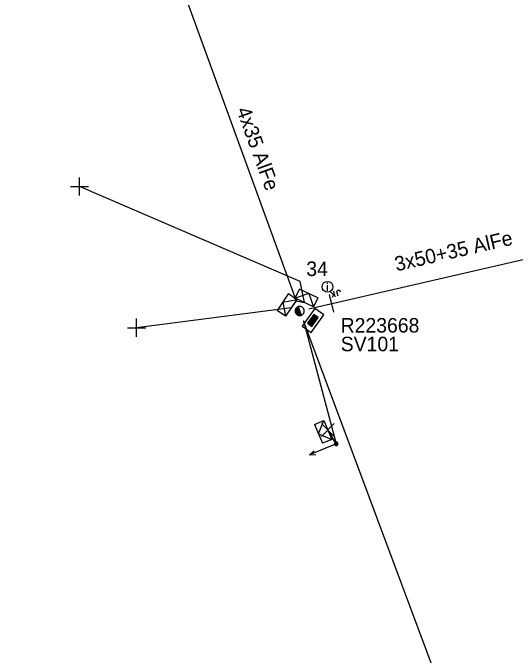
# Model space of a CAD drawing. Extents: x -536148 to -535465, y -1201639 to -1201298.
# Drawn here: x -535581.57 to -535546.95, y -1201567.67 to -1201523.39 of the extents above; entities that cross this region are included whole.
import ezdxf

# ---------------------------------------------------------------- set-up
doc = ezdxf.new("R2010")
doc.units = 0
for name, color, linetype in [('CHRAN_NN', 7, 'Continuous'), ('CIZÍ_NADZEM_POPIS', 7, 'Continuous'), ('CIZÍ_PODZEM', 7, 'Continuous'), ('CIZÍ_PODZEM_POPIS', 7, 'Continuous'), ('DOPLŇ_POPISY', 7, 'Continuous'), ('ELE_EON', 7, 'Continuous'), ('ELE_EON_POPIS', 7, 'Continuous'), ('KN_HRAN_POHYBLIVÁ', 7, 'Continuous'), ('KN_VKP_HRAN_', 7, 'Continuous'), ('KN_VKP_HRAN_NEZNATELNÁ', 7, 'Continuous'), ('KN_VKP_HRAN_PARCEL_NEVIDITELNÁ', 7, 'Continuous'), ('KN_VKP_HRAN_SPORNÁ', 7, 'Continuous'), ('OP KABELU NN', 7, 'Continuous'), ('PB_NN_POPIS', 7, 'Continuous'), ('PK_HRAN_POHYBLIVÁ', 7, 'Continuous'), ('PLG_EXPORT_GPE', 7, 'Continuous'), ('RÁMEČEK', 7, 'Continuous')]:
    doc.layers.add(name, color=color, linetype=linetype)

# ---------------------------------------------------------------- blocks, each defined once
blk = doc.blocks.new('NN440')
at = {"layer": 'ELE_EON_POPIS'}
for points in [[(0.631, -0.004), (0.627, 0.062), (0.617, 0.127), (0.6, 0.191), (0.577, 0.252), (0.547, 0.311), (0.511, 0.366), (0.469, 0.417), (0.423, 0.464), (0.371, 0.505), (0.316, 0.542), (0.257, 0.571), (0.196, 0.595), (0.132, 0.612), (0.067, 0.622), (0.001, 0.626), (-0.065, 0.622), (-0.13, 0.612), (-0.194, 0.595), (-0.255, 0.571), (-0.314, 0.542), (-0.369, 0.505), (-0.42, 0.464), (-0.467, 0.417), (-0.509, 0.366), (-0.544, 0.311), (-0.574, 0.252), (-0.598, 0.191), (-0.615, 0.127), (-0.626, 0.062), (-0.629, -0.004), (-0.626, -0.07), (-0.615, -0.135), (-0.598, -0.199), (-0.574, -0.26), (-0.544, -0.319), (-0.509, -0.374), (-0.467, -0.426), (-0.42, -0.472), (-0.369, -0.514), (-0.314, -0.55), (-0.255, -0.58), (-0.194, -0.603), (-0.13, -0.62), (-0.065, -0.631), (0.001, -0.634), (0.067, -0.631), (0.132, -0.62), (0.196, -0.603), (0.257, -0.58), (0.316, -0.55), (0.371, -0.514), (0.423, -0.472), (0.469, -0.426), (0.511, -0.374), (0.547, -0.319), (0.577, -0.26), (0.6, -0.199), (0.617, -0.135), (0.627, -0.07), (0.631, -0.004)], [(-0.631, 0), (0.629, 0)], [(-0.601, -0.177), (0.57, -0.177)], [(-0.513, -0.325), (0.501, -0.325)], [(-0.375, -0.473), (0.353, -0.473)]]:
    blk.add_lwpolyline(points, dxfattribs=at)
blk = doc.blocks.new('NN560')
at = {"layer": 'ELE_EON_POPIS'}
for points in [[(1.999, -0.001), (1.59, 0.141)], [(0, -0.001), (1.999, -0.001)], [(1.999, -0.001), (1.59, -0.134)]]:
    blk.add_lwpolyline(points, dxfattribs=at)
blk = doc.blocks.new('NN840')
at = {"layer": 'RÁMEČEK'}
for points in [[(0.003, 0.619), (0.003, -0.631)], [(-0.538, -0.385), (-0.538, -0.71)], [(-0.332, -0.385), (-0.332, -0.798)], [(-0.332, -0.641), (-0.125, -0.385)], [(-0.745, -0.71), (-0.745, -0.66)], [(-0.73, -0.764), (-0.745, -0.71)], [(-0.657, -0.798), (-0.73, -0.764)], [(-0.627, -0.798), (-0.657, -0.798)], [(-0.558, -0.764), (-0.627, -0.798)], [(-0.538, -0.71), (-0.558, -0.764)], [(-0.263, -0.557), (-0.091, -0.798)]]:
    blk.add_lwpolyline(points, dxfattribs=at)
blk = doc.blocks.new('NN770')
at = {"layer": 'CIZÍ_PODZEM_POPIS'}
for p, q in [((0.002, 0.187), (0.002, 0.263)), ((0.002, -0.276), (0.002, 0.111))]:
    blk.add_line(p, q, dxfattribs=at)
blk.add_circle((0, -0.008), 0.375, dxfattribs=at)
blk = doc.blocks.new('NN800')
at = {"layer": 'ELE_EON'}
for points in [[(-0.442, 0.442), (0.442, -0.442)], [(-0.442, -0.442), (0.442, 0.442)]]:
    blk.add_lwpolyline(points, dxfattribs=at)
blk = doc.blocks.new('NN620')
at = {"layer": 'CIZÍ_NADZEM_POPIS'}
for points in [[(0.752, 0.004), (-0.748, 0.004)], [(-0.748, 0.004), (-0.748, -0.746)], [(0.752, -0.746), (0.752, 0.004)], [(0.368, -0.18), (-0.376, -0.18)], [(-0.376, -0.18), (-0.376, -0.558)], [(0.321, -0.227), (-0.329, -0.227)], [(-0.329, -0.227), (-0.329, -0.51)], [(0.274, -0.274), (-0.281, -0.274)], [(-0.281, -0.274), (-0.281, -0.463)], [(0.227, -0.321), (-0.234, -0.321)], [(-0.234, -0.321), (-0.234, -0.416)], [(-0.234, -0.416), (0.227, -0.416)], [(-0.193, -0.369), (0.185, -0.369)], [(0.227, -0.416), (0.227, -0.321)], [(0.274, -0.463), (0.274, -0.274)], [(0.321, -0.51), (0.321, -0.227)], [(0.368, -0.558), (0.368, -0.18)], [(-0.748, -0.746), (0.752, -0.746)], [(-0.376, -0.558), (0.368, -0.558)], [(-0.329, -0.51), (0.321, -0.51)], [(-0.281, -0.463), (0.274, -0.463)]]:
    blk.add_lwpolyline(points, dxfattribs=at)
blk = doc.blocks.new('NN630')
at = {"layer": 'CIZÍ_PODZEM'}
for points in [[(-0.003, -0.7), (-0.703, 0)], [(-0.703, -0.7), (-0.703, 0), (0.697, 0), (0.697, -0.7)], [(-0.003, -0.7), (0.697, 0)], [(-0.703, -0.7), (0.697, -0.7)]]:
    blk.add_lwpolyline(points, dxfattribs=at)
blk = doc.blocks.new('NN500')
at = {"layer": 'ELE_EON_POPIS'}
for points in [[(-0.001, -0.235), (0.023, -0.234), (0.048, -0.23), (0.071, -0.224), (0.094, -0.215), (0.116, -0.204), (0.137, -0.191), (0.156, -0.175), (0.173, -0.158), (0.189, -0.139), (0.202, -0.118), (0.213, -0.096), (0.222, -0.073), (0.229, -0.049), (0.232, -0.025), (0.234, 0), (0.232, 0.024), (0.229, 0.048), (0.222, 0.072), (0.213, 0.095), (0.202, 0.117), (0.189, 0.138), (0.173, 0.157), (0.156, 0.174), (0.137, 0.19), (0.116, 0.203), (0.094, 0.214), (0.071, 0.223), (0.048, 0.229), (0.023, 0.233), (-0.001, 0.235), (-0.026, 0.233), (-0.05, 0.229), (-0.074, 0.223), (-0.097, 0.214), (-0.119, 0.203), (-0.139, 0.19), (-0.158, 0.174), (-0.176, 0.157), (-0.191, 0.138), (-0.205, 0.117), (-0.216, 0.095), (-0.225, 0.072), (-0.231, 0.048), (-0.235, 0.024), (-0.236, 0), (-0.235, -0.025), (-0.231, -0.049), (-0.225, -0.073), (-0.216, -0.096), (-0.205, -0.118), (-0.191, -0.139), (-0.176, -0.158), (-0.158, -0.175), (-0.139, -0.191), (-0.119, -0.204), (-0.097, -0.215), (-0.074, -0.224), (-0.05, -0.23), (-0.026, -0.234), (-0.001, -0.235)], [(-0.001, -0.235), (0.023, -0.234), (0.048, -0.23), (0.071, -0.224), (0.094, -0.215), (0.116, -0.204), (0.137, -0.191), (0.156, -0.175), (0.173, -0.158), (0.189, -0.139), (0.202, -0.118), (0.213, -0.096), (0.222, -0.073), (0.229, -0.049), (0.232, -0.025), (0.234, 0), (0.232, 0.024), (0.229, 0.048), (0.222, 0.072), (0.213, 0.095), (0.202, 0.117), (0.189, 0.138), (0.173, 0.157), (0.156, 0.174), (0.137, 0.19), (0.116, 0.203), (0.094, 0.214), (0.071, 0.223), (0.048, 0.229), (0.023, 0.233), (-0.001, 0.235), (-0.026, 0.233), (-0.05, 0.229), (-0.074, 0.223), (-0.097, 0.214), (-0.119, 0.203), (-0.139, 0.19), (-0.158, 0.174), (-0.176, 0.157), (-0.191, 0.138), (-0.205, 0.117), (-0.216, 0.095), (-0.225, 0.072), (-0.231, 0.048), (-0.235, 0.024), (-0.236, 0), (-0.235, -0.025), (-0.231, -0.049), (-0.225, -0.073), (-0.216, -0.096), (-0.205, -0.118), (-0.191, -0.139), (-0.176, -0.158), (-0.158, -0.175), (-0.139, -0.191), (-0.119, -0.204), (-0.097, -0.215), (-0.074, -0.224), (-0.05, -0.23), (-0.026, -0.234), (-0.001, -0.235)], [(-0.001, -0.206), (0.02, -0.205), (0.041, -0.201), (0.062, -0.196), (0.082, -0.188), (0.101, -0.178), (0.12, -0.167), (0.136, -0.153), (0.151, -0.138), (0.165, -0.121), (0.177, -0.103), (0.186, -0.084), (0.194, -0.064), (0.2, -0.043), (0.203, -0.022), (0.204, 0), (0.203, 0.021), (0.2, 0.042), (0.194, 0.063), (0.186, 0.083), (0.177, 0.102), (0.165, 0.12), (0.151, 0.137), (0.136, 0.152), (0.12, 0.166), (0.101, 0.177), (0.082, 0.187), (0.062, 0.195), (0.041, 0.2), (0.02, 0.204), (-0.001, 0.205), (-0.023, 0.204), (-0.044, 0.2), (-0.065, 0.195), (-0.085, 0.187), (-0.104, 0.177), (-0.122, 0.166), (-0.139, 0.152), (-0.154, 0.137), (-0.167, 0.12), (-0.179, 0.102), (-0.189, 0.083), (-0.197, 0.063), (-0.202, 0.042), (-0.205, 0.021), (-0.207, 0), (-0.205, -0.022), (-0.202, -0.043), (-0.197, -0.064), (-0.189, -0.084), (-0.179, -0.103), (-0.167, -0.121), (-0.154, -0.138), (-0.139, -0.153), (-0.122, -0.167), (-0.104, -0.178), (-0.085, -0.188), (-0.065, -0.196), (-0.044, -0.201), (-0.023, -0.205), (-0.001, -0.206)], [(-0.001, -0.176), (0.017, -0.175), (0.035, -0.172), (0.053, -0.168), (0.07, -0.161), (0.087, -0.153), (0.102, -0.143), (0.116, -0.131), (0.129, -0.118), (0.141, -0.104), (0.151, -0.088), (0.159, -0.072), (0.166, -0.055), (0.171, -0.037), (0.174, -0.019), (0.175, 0), (0.174, 0.018), (0.171, 0.036), (0.166, 0.054), (0.159, 0.071), (0.151, 0.087), (0.141, 0.103), (0.129, 0.117), (0.116, 0.13), (0.102, 0.142), (0.087, 0.152), (0.07, 0.16), (0.053, 0.167), (0.035, 0.172), (0.017, 0.174), (-0.001, 0.175), (-0.02, 0.174), (-0.038, 0.172), (-0.056, 0.167), (-0.073, 0.16), (-0.089, 0.152), (-0.105, 0.142), (-0.119, 0.13), (-0.132, 0.117), (-0.143, 0.103), (-0.153, 0.087), (-0.162, 0.071), (-0.168, 0.054), (-0.173, 0.036), (-0.176, 0.018), (-0.177, 0), (-0.176, -0.019), (-0.173, -0.037), (-0.168, -0.055), (-0.162, -0.072), (-0.153, -0.088), (-0.143, -0.104), (-0.132, -0.118), (-0.119, -0.131), (-0.105, -0.143), (-0.089, -0.153), (-0.073, -0.161), (-0.056, -0.168), (-0.038, -0.172), (-0.02, -0.175), (-0.001, -0.176)], [(-0.001, -0.147), (0.014, -0.146), (0.029, -0.143), (0.044, -0.139), (0.058, -0.134), (0.072, -0.127), (0.085, -0.119), (0.097, -0.109), (0.107, -0.098), (0.117, -0.086), (0.125, -0.073), (0.132, -0.06), (0.138, -0.046), (0.142, -0.031), (0.144, -0.016), (0.145, 0), (0.144, 0.015), (0.142, 0.03), (0.138, 0.045), (0.132, 0.059), (0.125, 0.073), (0.117, 0.086), (0.107, 0.097), (0.097, 0.108), (0.085, 0.118), (0.072, 0.126), (0.058, 0.133), (0.044, 0.139), (0.029, 0.143), (0.014, 0.145), (-0.001, 0.146), (-0.017, 0.145), (-0.032, 0.143), (-0.046, 0.139), (-0.061, 0.133), (-0.074, 0.126), (-0.087, 0.118), (-0.099, 0.108), (-0.11, 0.097), (-0.119, 0.086), (-0.128, 0.073), (-0.135, 0.059), (-0.14, 0.045), (-0.144, 0.03), (-0.147, 0.015), (-0.147, 0), (-0.147, -0.016), (-0.144, -0.031), (-0.14, -0.046), (-0.135, -0.06), (-0.128, -0.073), (-0.119, -0.086), (-0.11, -0.098), (-0.099, -0.109), (-0.087, -0.119), (-0.074, -0.127), (-0.061, -0.134), (-0.046, -0.139), (-0.032, -0.143), (-0.017, -0.146), (-0.001, -0.147)], [(-0.001, -0.117), (0.011, -0.116), (0.023, -0.114), (0.035, -0.111), (0.046, -0.107), (0.057, -0.101), (0.067, -0.095), (0.077, -0.087), (0.085, -0.078), (0.093, -0.069), (0.1, -0.059), (0.105, -0.048), (0.11, -0.036), (0.113, -0.025), (0.115, -0.013), (0.115, 0), (0.115, 0.012), (0.113, 0.024), (0.11, 0.036), (0.105, 0.047), (0.1, 0.058), (0.093, 0.068), (0.085, 0.078), (0.077, 0.086), (0.067, 0.094), (0.057, 0.101), (0.046, 0.106), (0.035, 0.11), (0.023, 0.114), (0.011, 0.116), (-0.001, 0.116), (-0.013, 0.116), (-0.025, 0.114), (-0.037, 0.11), (-0.049, 0.106), (-0.059, 0.101), (-0.07, 0.094), (-0.079, 0.086), (-0.088, 0.078), (-0.096, 0.068), (-0.102, 0.058), (-0.108, 0.047), (-0.112, 0.036), (-0.115, 0.024), (-0.117, 0.012), (-0.118, 0), (-0.117, -0.013), (-0.115, -0.025), (-0.112, -0.036), (-0.108, -0.048), (-0.102, -0.059), (-0.096, -0.069), (-0.088, -0.078), (-0.079, -0.087), (-0.07, -0.095), (-0.059, -0.101), (-0.049, -0.107), (-0.037, -0.111), (-0.025, -0.114), (-0.013, -0.116), (-0.001, -0.117)], [(-0.001, -0.087), (0.008, -0.087), (0.017, -0.085), (0.026, -0.083), (0.034, -0.08), (0.042, -0.076), (0.05, -0.071), (0.057, -0.065), (0.063, -0.059), (0.069, -0.051), (0.074, -0.044), (0.078, -0.036), (0.081, -0.027), (0.084, -0.019), (0.085, -0.01), (0.086, 0), (0.085, 0.009), (0.084, 0.018), (0.081, 0.026), (0.078, 0.035), (0.074, 0.043), (0.069, 0.051), (0.063, 0.058), (0.057, 0.064), (0.05, 0.07), (0.042, 0.075), (0.034, 0.079), (0.026, 0.082), (0.017, 0.085), (0.008, 0.086), (-0.001, 0.087), (-0.01, 0.086), (-0.019, 0.085), (-0.028, 0.082), (-0.037, 0.079), (-0.045, 0.075), (-0.052, 0.07), (-0.059, 0.064), (-0.066, 0.058), (-0.072, 0.051), (-0.077, 0.043), (-0.081, 0.035), (-0.084, 0.026), (-0.086, 0.018), (-0.088, 0.009), (-0.088, 0), (-0.088, -0.01), (-0.086, -0.019), (-0.084, -0.027), (-0.081, -0.036), (-0.077, -0.044), (-0.072, -0.052), (-0.066, -0.059), (-0.059, -0.065), (-0.052, -0.071), (-0.045, -0.076), (-0.037, -0.08), (-0.028, -0.083), (-0.019, -0.085), (-0.01, -0.087), (-0.001, -0.087)], [(-0.001, -0.058), (0.005, -0.057), (0.011, -0.056), (0.016, -0.055), (0.022, -0.053), (0.027, -0.05), (0.032, -0.047), (0.037, -0.043), (0.041, -0.039), (0.045, -0.034), (0.048, -0.029), (0.051, -0.024), (0.053, -0.018), (0.055, -0.012), (0.056, -0.006), (0.056, 0), (0.056, 0.006), (0.055, 0.011), (0.053, 0.017), (0.051, 0.023), (0.048, 0.028), (0.045, 0.033), (0.041, 0.038), (0.037, 0.042), (0.032, 0.046), (0.027, 0.049), (0.022, 0.052), (0.016, 0.054), (0.011, 0.056), (0.005, 0.057), (-0.001, 0.057), (-0.007, 0.057), (-0.013, 0.056), (-0.019, 0.054), (-0.025, 0.052), (-0.03, 0.049), (-0.035, 0.046), (-0.04, 0.042), (-0.044, 0.038), (-0.048, 0.033), (-0.051, 0.028), (-0.054, 0.023), (-0.056, 0.017), (-0.057, 0.011), (-0.058, 0.006), (-0.059, 0), (-0.058, -0.006), (-0.057, -0.012), (-0.056, -0.018), (-0.054, -0.024), (-0.051, -0.029), (-0.048, -0.034), (-0.044, -0.039), (-0.04, -0.043), (-0.035, -0.047), (-0.03, -0.05), (-0.025, -0.053), (-0.019, -0.055), (-0.013, -0.056), (-0.007, -0.057), (-0.001, -0.058)], [(-0.001, -0.028), (0.002, -0.028), (0.005, -0.028), (0.007, -0.027), (0.01, -0.026), (0.013, -0.024), (0.015, -0.023), (0.017, -0.021), (0.019, -0.019), (0.021, -0.017), (0.023, -0.014), (0.024, -0.012), (0.025, -0.009), (0.026, -0.006), (0.026, -0.003), (0.027, 0), (0.026, 0.002), (0.026, 0.005), (0.025, 0.008), (0.024, 0.011), (0.023, 0.013), (0.021, 0.016), (0.019, 0.018), (0.017, 0.02), (0.015, 0.022), (0.013, 0.024), (0.01, 0.025), (0.007, 0.026), (0.005, 0.027), (0.002, 0.027), (-0.001, 0.027), (-0.004, 0.027), (-0.007, 0.027), (-0.01, 0.026), (-0.012, 0.025), (-0.015, 0.024), (-0.018, 0.022), (-0.02, 0.02), (-0.022, 0.018), (-0.024, 0.016), (-0.025, 0.013), (-0.027, 0.011), (-0.028, 0.008), (-0.028, 0.005), (-0.029, 0.002), (-0.029, 0), (-0.029, -0.003), (-0.028, -0.006), (-0.028, -0.009), (-0.027, -0.012), (-0.025, -0.014), (-0.024, -0.017), (-0.022, -0.019), (-0.02, -0.021), (-0.018, -0.023), (-0.015, -0.024), (-0.012, -0.026), (-0.01, -0.027), (-0.007, -0.028), (-0.004, -0.028), (-0.001, -0.028)], [(0.234, 0), (0.704, 0)]]:
    blk.add_lwpolyline(points, dxfattribs=at)

msp = doc.modelspace()

# ---------------------------------------------------------------- linework, layer by layer
at = {"layer": 'CHRAN_NN'}
for points in [[(-535561.477, -1201543.362), (-535561.769, -1201541.904), (-535576.978, -1201535.361)], [(-535562.382, -1201543.723), (-535573.038, -1201545.098)]]:
    msp.add_lwpolyline(points, dxfattribs=at)
at = {"layer": 'ELE_EON'}
for points in [[(-535704.28, -1201335.78), (-535687.29, -1201370.27), (-535663.05, -1201399.63), (-535635.32, -1201433.41), (-535614.862, -1201457.774), (-535589.24, -1201487.744), (-535570.255, -1201520.699), (-535562.055, -1201543.241)], [(-535561.176, -1201543.795), (-535540.23, -1201538.98)], [(-535540.143, -1201611.931), (-535549.68, -1201576.4), (-535561.545, -1201544.626)]]:
    msp.add_lwpolyline(points, dxfattribs=at)
at = {"layer": 'PB_NN_POPIS'}
for points in [[(-535562.054, -1201543.241), (-535562.382, -1201543.723)], [(-535562.055, -1201543.241), (-535561.477, -1201543.362)], [(-535561.545, -1201544.626), (-535559.28, -1201553.1), (-535559.861, -1201552.148)]]:
    msp.add_lwpolyline(points, dxfattribs=at)

# ---------------------------------------------------------------- block references
at = {"layer": 'DOPLŇ_POPISY'}
for name, p, xscale, yscale, rotation in [('NN440', (-535561.8, -1201543.94), 0.5000000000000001, 0.5, -69.56942776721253), ('NN500', (-535559.28, -1201553.1), 0.49999999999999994, 0.5000000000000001, -157.36799995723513)]:
    msp.add_blockref(name, p, dxfattribs=dict(at, xscale=xscale, yscale=yscale, rotation=rotation))
at = {"layer": 'DOPLŇ_POPISY', "rotation": -157.3463943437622}
msp.add_blockref('NN560', (-535559.28, -1201553.1), dxfattribs=at)
at = {"layer": 'KN_HRAN_POHYBLIVÁ', "rotation": -166.92921039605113}
msp.add_blockref('NN840', (-535559.594, -1201543.428), dxfattribs=at)
at = {"layer": 'KN_VKP_HRAN_NEZNATELNÁ'}
for p, rotation in [((-535576.978, -1201535.362), 44.999999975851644), ((-535573.038, -1201545.098), 45)]:
    msp.add_blockref('NN800', p, dxfattribs=dict(at, rotation=rotation))
msp.add_blockref('NN800', (-535559.861, -1201552.148), dxfattribs=at)
at = {"layer": 'KN_VKP_HRAN_SPORNÁ'}
for p, rotation in [((-535562.382, -1201543.723), -124.23520557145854), ((-535561.476, -1201543.363), 154.93494158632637), ((-535559.861, -1201552.148), -67.39208054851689)]:
    msp.add_blockref('NN630', p, dxfattribs=dict(at, rotation=rotation))
at = {"layer": 'OP KABELU NN', "rotation": 54.43099991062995}
msp.add_blockref('NN620', (-535561.19, -1201544.377), dxfattribs=at)
at = {"layer": 'PK_HRAN_POHYBLIVÁ'}
msp.add_blockref('NN770', (-535559.885, -1201542.269), dxfattribs=at)

# ---------------------------------------------------------------- texts
at = {"layer": 'ELE_EON_POPIS'}
for s, rotation, p in [('4x35 AlFe', 289.977, (-535566.176, -1201530.086)), ('3x50+35 AlFe', 12.946, (-535555.132, -1201541.217))]:
    msp.add_text(s, height=1, rotation=rotation, dxfattribs=at).set_placement(p)
at = {"layer": 'KN_VKP_HRAN_'}
msp.add_text('SV101', height=1, dxfattribs=at).set_placement((-535558.973, -1201546.718))
at = {"layer": 'KN_VKP_HRAN_PARCEL_NEVIDITELNÁ'}
msp.add_text('R223668', height=1, dxfattribs=at).set_placement((-535558.98, -1201545.43))
at = {"layer": 'PLG_EXPORT_GPE'}
msp.add_text('34', height=1, dxfattribs=at).set_placement((-535561.347, -1201541.534))

doc.saveas('drawing.dxf')
